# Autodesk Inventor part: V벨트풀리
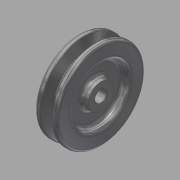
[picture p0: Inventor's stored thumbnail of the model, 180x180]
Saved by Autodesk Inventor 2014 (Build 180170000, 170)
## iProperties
Created: 2015-11
Part Number: V벨트풀리
Material: 강철, 탄소
Document SubType Name: Modeling
Designer: mduedu
Density: 1 g/cm^3
Appearance: 반광택
Author: mduedu
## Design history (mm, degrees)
sketch "스케치1"
  geometry: L1 (-9.5, 0)-(9.5, 0); L2 (0, 0)-(0, 37.7); L3 (-4.825, 37.7)-(-9.5, 37.7); L4 (-9.5, 37.7)-(-9.5, 0); L5 (0, 28.7)-(-2.074, 28.7); L6 (-2.074, 28.7)-(-4.825, 37.7); L7 (4.825, 37.7)-(9.5, 37.7); L8 (9.5, 37.7)-(9.5, 0); L9 (0, 28.7)-(2.074, 28.7); L10 (2.074, 28.7)-(4.825, 37.7); L11 (-9.5, 35)-(9.5, 35); 3 further points
  constraints: 22 end point, 7 point on line, 4 perpendicular, 3 symmetric about line, 1 coincident, 1 horizontal, 1 horizontal alignment, 1 midpoint, 1 vertical
  dimensions: "d0" = 19 distance of L1.start L1.end; "d2" = 75.4 diameter of L2.end L1 (derived); "d3" = 34 deg angle of L10 L6; "d4" = 6.3 distance between parallel lines of L11 L9; "d5" = 2.7 distance between parallel lines of L7 L11; "d6" = 8 distance of point (4, 35) point (-4, 35); "d7" = 70 diameter of L11 L1
revolve "회전1" sketch "스케치1" stored, may be unused: angle "d8" = 90 deg
sketch "스케치2"
  geometry: C1 r 24 at (0, 0); C2 r 11 at (0, 0); 1 further point
  constraints: 2 centre point, 2 coincident
  dimensions: "d9" = 48 diameter of C1; "d10" = 22 diameter of C2
extrude "돌출1" cut sketch "스케치2" distance "d11" = 6; taper "d12" = 0 deg
fillet "모깎기1" dims "d13" = 3
fillet "모깎기2" dims "d14" = 3
fillet "모깎기3" dims "d15" = 1, "d16" = 0.5, "d17" = 2
hole "구멍1" diameter "d20" = 10; stored, may be unused: countersink angle "d24" = 90 deg, drill point angle "d26" = 118 deg; dims "d18" = 10, "d19" = 10, "d21" = 6, "d22" = 4, "d23" = 2, "d25" = 8
sketch "스케치3"
  geometry: L1 (-1.5, 0)-(1.5, 0); L2 (1.5, 0)-(1.5, 6.4); L3 (1.5, 6.4)-(-1.5, 6.4); L4 (-1.5, 6.4)-(-1.5, 0); 2 further points
  constraints: 8 end point, 2 parallel, 1 coincident, 1 horizontal, 1 midpoint, 1 perpendicular
  dimensions: "d27" = 3 distance of L2.end L3.end; "d29" = 6.4 distance of L3.end L1.start
extrude "돌출2" cut sketch "스케치3" stored distance "d30" = 6; taper "d31" = 0 deg
chamfer "모따기1" distance "d32" = 0.5; stored, may be unused: second distance "d33" = 2, angle "d34" = 45 deg
node "솔리드1"
mirror "대칭1"
